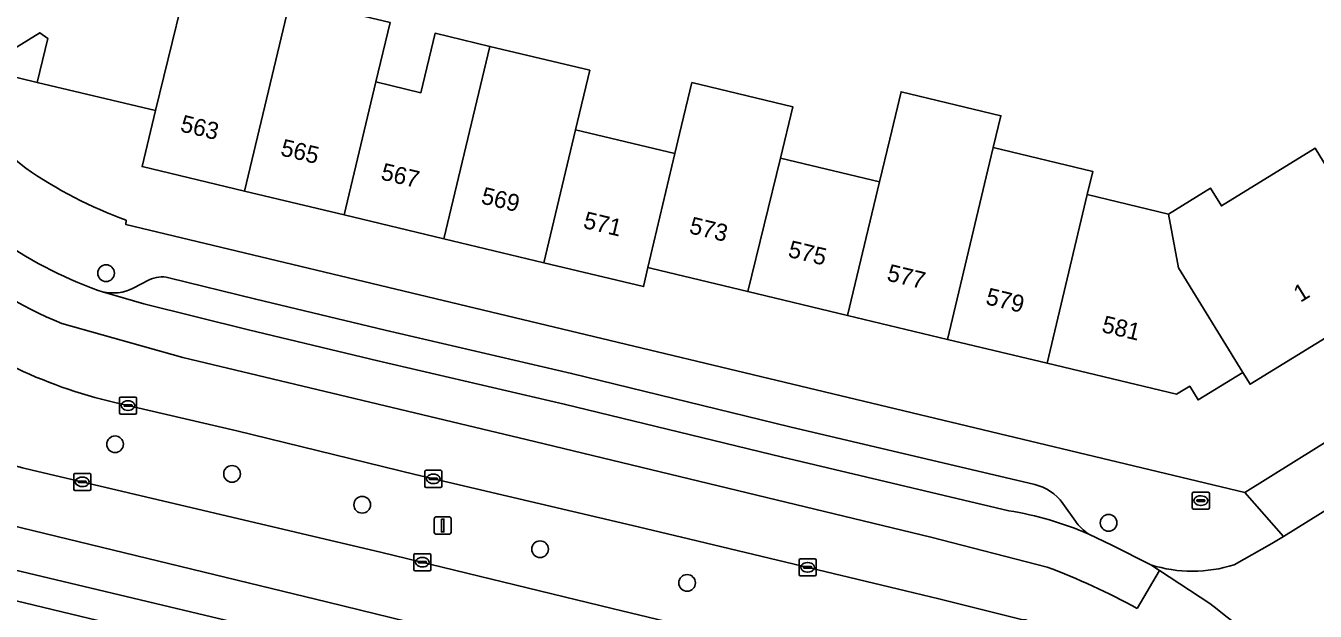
# Model space of a CAD drawing. Extents: x 157767 to 159172, y 387839 to 389425.
# Drawn here: x 158644.5 to 158720.1, y 388142.5 to 388176.8 of the extents above; entities that cross this region are included whole.
import ezdxf

# ---------------------------------------------------------------- set-up
doc = ezdxf.new("R2010")
doc.units = 0
for name, color, linetype in [('IMGEO_Berm_groen', 7, 'Continuous'), ('IMGEO_Boom', 7, 'Continuous'), ('IMGEO_Brandkraan', 7, 'Continuous'), ('IMGEO_Erf', 7, 'Continuous'), ('IMGEO_Kolk', 7, 'Continuous'), ('IMGEO_Lichtmast', 7, 'Continuous'), ('IMGEO_Pand', 7, 'Continuous'), ('IMGEO_Pand_nummerreeks', 7, 'Continuous'), ('IMGEO_Pand_overbouw', 7, 'Continuous'), ('IMGEO_Parkeervlak_open', 7, 'Continuous'), ('IMGEO_Rijbaan_lokaal_gesloten', 7, 'Continuous'), ('IMGEO_Rijbaan_lokaal_open', 7, 'Continuous'), ('IMGEO_Voetpad_open', 7, 'Continuous')]:
    doc.layers.add(name, color=color, linetype=linetype)

msp = doc.modelspace()

# ---------------------------------------------------------------- linework, layer by layer
at = {"layer": 'IMGEO_Berm_groen'}
for points in [[(158667.296, 388150.548), (158656.841, 388153.114), (158649.695, 388154.768)], [(158645.432, 388150.672), (158665.345, 388145.992), (158678.854, 388142.706), (158696.862, 388138.362), (158697.567, 388138.192), (158699.866, 388138.031)], [(158702.855, 388142.067), (158698.004, 388143.26), (158696.05, 388143.74), (158682.917, 388146.888), (158680.041, 388147.562), (158667.296, 388150.548)]]:
    msp.add_lwpolyline(points, dxfattribs=at)
for centre, radius, start, end in [((158656.169, 388182.727), 28.699, 231.06301, 256.96233), ((158651.465, 388178.109), 28.093, 238.29474, 257.59871)]:
    msp.add_arc(centre, radius, start, end, dxfattribs=at)
at = {"layer": 'IMGEO_Boom'}
for centre in [(158649.176, 388162.346), (158649.706, 388152.323), (158656.563, 388150.59), (158664.196, 388148.781), (158707.96, 388147.722), (158674.622, 388146.175), (158683.245, 388144.202)]:
    msp.add_circle(centre, 0.489, dxfattribs=at)
at = {"layer": 'IMGEO_Brandkraan'}
for p, q in [((158712.865, 388148.597), (158712.865, 388149.449)), ((158712.94, 388149.523), (158713.792, 388149.523)), ((158713.353, 388149.303), (158713.378, 388149.303)), ((158713.866, 388149.449), (158713.866, 388148.597)), ((158713.124, 388149.017), (158713.124, 388149.029)), ((158713.562, 388148.98), (158713.164, 388148.98)), ((158713.167, 388149.066), (158713.565, 388149.066)), ((158713.376, 388148.743), (158713.351, 388148.743)), ((158713.608, 388149.029), (158713.608, 388149.017)), ((158713.792, 388148.523), (158712.94, 388148.523))]:
    msp.add_line(p, q, dxfattribs=at)
for points in [[(158712.865, 388148.597), (158712.865, 388149.449)], [(158712.94, 388149.523), (158713.792, 388149.523)], [(158713.866, 388149.449), (158713.866, 388148.597)], [(158713.792, 388148.523), (158712.94, 388148.523)]]:
    msp.add_lwpolyline(points, dxfattribs=at)
for centre, radius, start, end in [((158712.942, 388149.447), 0.0765, 91.55205, 178.44795), ((158712.942, 388149.447), 0.0765, 91.55205, 178.44795), ((158713.79, 388149.447), 0.0765, 1.55205, 88.44795), ((158713.79, 388149.447), 0.0765, 1.55205, 88.44795), ((158712.942, 388148.599), 0.0765, 181.55205, 268.44795), ((158712.942, 388148.599), 0.0765, 181.55205, 268.44795), ((158713.164, 388149.026), 0.0403, 85.87752, 175.75265), ((158713.161, 388149.016), 0.0366, 178.93798, 274.71019), ((158713.565, 388149.023), 0.043, 264.86636, 352.45326), ((158713.569, 388149.028), 0.0386, 1.73085, 96.63898), ((158713.79, 388148.599), 0.0765, 271.55205, 358.44795), ((158713.79, 388148.599), 0.0765, 271.55205, 358.44795)]:
    msp.add_arc(centre, radius, start, end, dxfattribs=at)
for centre, major_axis, ratio, start_param, end_param in [((158713.352, 388149.023), (-0.387, 0.002), 0.722429, 4.712389, 7.853982), ((158713.377, 388149.023), (-0.39, 0.002), 0.717154, 1.570796, 4.712389)]:
    msp.add_ellipse(centre, major_axis=major_axis, ratio=ratio, start_param=start_param, end_param=end_param, dxfattribs=at)
at = {"layer": 'IMGEO_Erf'}
for points in [[(158650.367, 388165.452), (158650.337, 388165.203), (158715.951, 388149.492), (158768.176, 388182.052)], [(158665.837, 388177.027), (158665.004, 388173.549), (158667.637, 388172.919), (158668.469, 388176.398), (158671.687, 388175.628), (158677.536, 388174.228), (158676.704, 388170.749), (158682.532, 388169.354), (158682.806, 388170.501), (158683.525, 388173.507), (158689.436, 388172.093), (158688.717, 388169.087), (158694.528, 388167.696), (158695.127, 388170.2), (158695.79, 388172.971), (158701.64, 388171.572), (158701.192, 388169.7), (158707.027, 388168.305), (158706.703, 388166.947), (158711.467, 388165.807), (158713.927, 388167.33), (158714.573, 388166.287), (158720.07, 388169.662), (158721.758, 388166.913)], [(158725.067, 388161.247), (158716.251, 388155.836), (158715.824, 388156.53), (158713.204, 388154.921), (158712.713, 388155.722), (158711.947, 388155.252), (158704.35, 388157.07), (158698.505, 388158.469), (158692.655, 388159.869), (158686.804, 388161.269), (158681.174, 388162.616), (158680.952, 388162.669), (158680.689, 388161.556), (158674.839, 388162.956), (158668.989, 388164.356), (158663.139, 388165.756), (158657.29, 388167.155), (158651.29, 388168.591), (158652.073, 388171.866), (158645.146, 388173.524), (158645.761, 388176.093), (158645.303, 388176.425), (158643.052, 388175.044)]]:
    msp.add_lwpolyline(points, dxfattribs=at)
for centre, radius, start, end in [((158660.881, 388188.822), 26.124, 210.21415, 231.08824), ((158658.967, 388189.344), 25.393, 235.19125, 250.20316)]:
    msp.add_arc(centre, radius, start, end, dxfattribs=at)
at = {"layer": 'IMGEO_Kolk'}
for p, q in [((158649.966, 388154.165), (158649.966, 388155.017)), ((158650.041, 388155.091), (158650.893, 388155.091)), ((158650.225, 388154.585), (158650.225, 388154.597)), ((158650.268, 388154.634), (158650.666, 388154.634)), ((158650.454, 388154.871), (158650.479, 388154.871)), ((158650.709, 388154.597), (158650.709, 388154.585)), ((158650.967, 388155.017), (158650.967, 388154.165)), ((158650.893, 388154.091), (158650.041, 388154.091)), ((158650.663, 388154.548), (158650.265, 388154.548)), ((158650.477, 388154.311), (158650.452, 388154.311)), ((158647.282, 388149.695), (158647.282, 388150.547)), ((158647.357, 388150.621), (158648.209, 388150.621)), ((158647.541, 388150.115), (158647.541, 388150.127)), ((158647.979, 388150.078), (158647.581, 388150.078)), ((158647.584, 388150.164), (158647.982, 388150.164)), ((158647.77, 388150.401), (158647.795, 388150.401)), ((158648.025, 388150.127), (158648.025, 388150.115)), ((158648.283, 388150.547), (158648.283, 388149.695)), ((158667.864, 388149.871), (158667.864, 388150.723)), ((158667.939, 388150.797), (158668.791, 388150.797)), ((158668.123, 388150.291), (158668.123, 388150.303)), ((158668.561, 388150.254), (158668.163, 388150.254)), ((158668.166, 388150.34), (158668.564, 388150.34)), ((158668.352, 388150.577), (158668.377, 388150.577)), ((158668.607, 388150.303), (158668.607, 388150.291)), ((158668.865, 388150.723), (158668.865, 388149.871)), ((158648.209, 388149.621), (158647.357, 388149.621)), ((158647.793, 388149.841), (158647.768, 388149.841)), ((158668.791, 388149.797), (158667.939, 388149.797)), ((158668.375, 388150.017), (158668.35, 388150.017)), ((158667.222, 388144.989), (158667.222, 388145.841)), ((158667.297, 388145.915), (158668.149, 388145.915)), ((158667.71, 388145.695), (158667.735, 388145.695)), ((158668.223, 388145.841), (158668.223, 388144.989)), ((158689.812, 388144.688), (158689.812, 388145.54)), ((158689.887, 388145.614), (158690.739, 388145.614)), ((158690.813, 388145.54), (158690.813, 388144.688)), ((158668.149, 388144.915), (158667.297, 388144.915)), ((158667.481, 388145.409), (158667.481, 388145.421)), ((158667.919, 388145.372), (158667.521, 388145.372)), ((158667.524, 388145.458), (158667.922, 388145.458)), ((158667.733, 388145.135), (158667.708, 388145.135)), ((158667.965, 388145.421), (158667.965, 388145.409)), ((158690.071, 388145.108), (158690.071, 388145.12)), ((158690.509, 388145.071), (158690.111, 388145.071)), ((158690.114, 388145.157), (158690.512, 388145.157)), ((158690.323, 388144.834), (158690.298, 388144.834)), ((158690.3, 388145.394), (158690.325, 388145.394)), ((158690.555, 388145.12), (158690.555, 388145.108)), ((158690.739, 388144.614), (158689.887, 388144.614))]:
    msp.add_line(p, q, dxfattribs=at)
for points in [[(158649.966, 388154.165), (158649.966, 388155.017)], [(158650.041, 388155.091), (158650.893, 388155.091)], [(158650.967, 388155.017), (158650.967, 388154.165)], [(158650.893, 388154.091), (158650.041, 388154.091)], [(158647.282, 388149.695), (158647.282, 388150.547)], [(158647.357, 388150.621), (158648.209, 388150.621)], [(158648.283, 388150.547), (158648.283, 388149.695)], [(158667.864, 388149.871), (158667.864, 388150.723)], [(158667.939, 388150.797), (158668.791, 388150.797)], [(158668.865, 388150.723), (158668.865, 388149.871)], [(158648.209, 388149.621), (158647.357, 388149.621)], [(158668.791, 388149.797), (158667.939, 388149.797)], [(158667.222, 388144.989), (158667.222, 388145.841)], [(158667.297, 388145.915), (158668.149, 388145.915)], [(158668.223, 388145.841), (158668.223, 388144.989)], [(158689.812, 388144.688), (158689.812, 388145.54)], [(158689.887, 388145.614), (158690.739, 388145.614)], [(158690.813, 388145.54), (158690.813, 388144.688)], [(158668.149, 388144.915), (158667.297, 388144.915)], [(158690.739, 388144.614), (158689.887, 388144.614)]]:
    msp.add_lwpolyline(points, dxfattribs=at)
for centre, radius, start, end in [((158650.043, 388155.015), 0.0765, 91.55205, 178.44795), ((158650.043, 388155.015), 0.0765, 91.55205, 178.44795), ((158650.265, 388154.594), 0.0403, 85.87752, 175.75265), ((158650.67, 388154.596), 0.0386, 1.73085, 96.63898), ((158650.891, 388155.015), 0.0765, 1.55205, 88.44795), ((158650.891, 388155.015), 0.0765, 1.55205, 88.44795), ((158650.043, 388154.167), 0.0765, 181.55205, 268.44795), ((158650.043, 388154.167), 0.0765, 181.55205, 268.44795), ((158650.262, 388154.584), 0.0366, 178.93798, 274.71019), ((158650.666, 388154.591), 0.043, 264.86636, 352.45326), ((158650.891, 388154.167), 0.0765, 271.55205, 358.44795), ((158650.891, 388154.167), 0.0765, 271.55205, 358.44795), ((158647.359, 388150.545), 0.0765, 91.55205, 178.44795), ((158647.359, 388150.545), 0.0765, 91.55205, 178.44795), ((158647.581, 388150.124), 0.0403, 85.87752, 175.75265), ((158647.578, 388150.114), 0.0366, 178.93798, 274.71019), ((158647.982, 388150.121), 0.043, 264.86636, 352.45326), ((158647.986, 388150.126), 0.0386, 1.73085, 96.63898), ((158648.207, 388150.545), 0.0765, 1.55205, 88.44795), ((158648.207, 388150.545), 0.0765, 1.55205, 88.44795), ((158667.941, 388150.721), 0.0765, 91.55205, 178.44795), ((158667.941, 388150.721), 0.0765, 91.55205, 178.44795), ((158668.163, 388150.3), 0.0403, 85.87752, 175.75265), ((158668.16, 388150.29), 0.0366, 178.93798, 274.71019), ((158668.564, 388150.297), 0.043, 264.86636, 352.45326), ((158668.568, 388150.302), 0.0386, 1.73085, 96.63898), ((158668.789, 388150.721), 0.0765, 1.55205, 88.44795), ((158668.789, 388150.721), 0.0765, 1.55205, 88.44795), ((158647.359, 388149.697), 0.0765, 181.55205, 268.44795), ((158647.359, 388149.697), 0.0765, 181.55205, 268.44795), ((158648.207, 388149.697), 0.0765, 271.55205, 358.44795), ((158648.207, 388149.697), 0.0765, 271.55205, 358.44795), ((158667.941, 388149.873), 0.0765, 181.55205, 268.44795), ((158667.941, 388149.873), 0.0765, 181.55205, 268.44795), ((158668.789, 388149.873), 0.0765, 271.55205, 358.44795), ((158668.789, 388149.873), 0.0765, 271.55205, 358.44795), ((158667.299, 388145.839), 0.0765, 91.55205, 178.44795), ((158667.299, 388145.839), 0.0765, 91.55205, 178.44795), ((158668.147, 388145.839), 0.0765, 1.55205, 88.44795), ((158668.147, 388145.839), 0.0765, 1.55205, 88.44795), ((158689.889, 388145.538), 0.0765, 91.55205, 178.44795), ((158689.889, 388145.538), 0.0765, 91.55205, 178.44795), ((158690.737, 388145.538), 0.0765, 1.55205, 88.44795), ((158690.737, 388145.538), 0.0765, 1.55205, 88.44795), ((158667.299, 388144.991), 0.0765, 181.55205, 268.44795), ((158667.299, 388144.991), 0.0765, 181.55205, 268.44795), ((158667.521, 388145.418), 0.0403, 85.87752, 175.75265), ((158667.518, 388145.408), 0.0366, 178.93798, 274.71019), ((158667.922, 388145.415), 0.043, 264.86636, 352.45326), ((158667.926, 388145.42), 0.0386, 1.73085, 96.63898), ((158668.147, 388144.991), 0.0765, 271.55205, 358.44795), ((158668.147, 388144.991), 0.0765, 271.55205, 358.44795), ((158690.111, 388145.117), 0.0403, 85.87752, 175.75265), ((158690.108, 388145.107), 0.0366, 178.93798, 274.71019), ((158690.512, 388145.114), 0.043, 264.86636, 352.45326), ((158690.516, 388145.119), 0.0386, 1.73085, 96.63898), ((158689.889, 388144.69), 0.0765, 181.55205, 268.44795), ((158689.889, 388144.69), 0.0765, 181.55205, 268.44795), ((158690.737, 388144.69), 0.0765, 271.55205, 358.44795), ((158690.737, 388144.69), 0.0765, 271.55205, 358.44795)]:
    msp.add_arc(centre, radius, start, end, dxfattribs=at)
for centre, major_axis, ratio, start_param, end_param in [((158650.453, 388154.591), (-0.387, 0.002), 0.722429, 4.712389, 7.853982), ((158650.478, 388154.591), (-0.39, 0.002), 0.717154, 1.570796, 4.712389), ((158647.769, 388150.121), (-0.387, 0.002), 0.722429, 4.712389, 7.853982), ((158647.794, 388150.121), (-0.39, 0.002), 0.717154, 1.570796, 4.712389), ((158668.351, 388150.297), (-0.387, 0.002), 0.722429, 4.712389, 7.853982), ((158668.376, 388150.297), (-0.39, 0.002), 0.717154, 1.570796, 4.712389), ((158667.709, 388145.415), (-0.387, 0.002), 0.722429, 4.712389, 7.853982), ((158667.734, 388145.415), (-0.39, 0.002), 0.717154, 1.570796, 4.712389), ((158690.299, 388145.114), (-0.387, 0.002), 0.722429, 4.712389, 7.853982), ((158690.324, 388145.114), (-0.39, 0.002), 0.717154, 1.570796, 4.712389)]:
    msp.add_ellipse(centre, major_axis=major_axis, ratio=ratio, start_param=start_param, end_param=end_param, dxfattribs=at)
at = {"layer": 'IMGEO_Lichtmast'}
for p, q in [((158668.421, 388147.165), (158668.421, 388147.965)), ((158668.421, 388147.965), (158668.421, 388147.165)), ((158668.521, 388148.065), (158669.311, 388148.065)), ((158669.311, 388148.065), (158668.521, 388148.065)), ((158669.411, 388147.965), (158669.411, 388147.165)), ((158669.411, 388147.165), (158669.411, 388147.965)), ((158669.311, 388147.065), (158668.521, 388147.065)), ((158668.521, 388147.065), (158669.311, 388147.065))]:
    msp.add_line(p, q, dxfattribs=at)
msp.add_lwpolyline([(158668.841, 388147.94), (158668.991, 388147.94), (158668.991, 388147.19), (158668.841, 388147.19), (158668.841, 388147.94)], dxfattribs=at)
for centre, start, end in [((158668.521, 388147.965), 90, 180), ((158668.521, 388147.965), 90, 180), ((158669.311, 388147.965), 0, 90), ((158669.311, 388147.965), 360, 90), ((158668.521, 388147.165), 180, 270), ((158668.521, 388147.165), 180, 270), ((158669.311, 388147.165), 270, 0), ((158669.311, 388147.165), 270, 0)]:
    msp.add_arc(centre, 0.1, start, end, dxfattribs=at)
at = {"layer": 'IMGEO_Pand'}
for points in [[(158654.026, 388179.853), (158653.869, 388179.891), (158654.069, 388180.729), (158649.399, 388181.847), (158647.073, 388185.635), (158639.217, 388180.813), (158639.28, 388180.711), (158639.493, 388180.842), (158643.052, 388175.044), (158645.303, 388176.425), (158645.761, 388176.093), (158645.146, 388173.524), (158652.073, 388171.866)], [(158657.29, 388167.155), (158659.988, 388178.427), (158654.026, 388179.853), (158652.073, 388171.866), (158651.29, 388168.591)], [(158665.004, 388173.549), (158665.837, 388177.027), (158659.988, 388178.427), (158657.29, 388167.155), (158663.139, 388165.756)], [(158671.687, 388175.628), (158668.469, 388176.398), (158667.637, 388172.919), (158665.004, 388173.549), (158663.139, 388165.756), (158668.989, 388164.356)], [(158676.704, 388170.749), (158677.536, 388174.228), (158671.687, 388175.628), (158668.989, 388164.356), (158674.839, 388162.956)], [(158688.717, 388169.087), (158689.436, 388172.093), (158683.525, 388173.507), (158682.806, 388170.501), (158682.532, 388169.354), (158680.952, 388162.669), (158681.174, 388162.616), (158686.804, 388161.269)], [(158700.977, 388168.801), (158701.192, 388169.7), (158701.64, 388171.572), (158695.79, 388172.971), (158695.127, 388170.2), (158694.528, 388167.696), (158692.655, 388159.869), (158698.505, 388158.469)], [(158682.532, 388169.354), (158676.704, 388170.749), (158674.839, 388162.956), (158680.689, 388161.556), (158680.952, 388162.669)], [(158686.804, 388161.269), (158692.655, 388159.869), (158694.528, 388167.696), (158688.717, 388169.087)], [(158700.977, 388168.801), (158698.505, 388158.469), (158704.35, 388157.07), (158706.703, 388166.947), (158707.027, 388168.305), (158701.192, 388169.7)], [(158721.758, 388166.913), (158720.07, 388169.662), (158714.573, 388166.287), (158713.927, 388167.33), (158711.467, 388165.807), (158712.066, 388162.649), (158715.824, 388156.53), (158716.251, 388155.836), (158725.067, 388161.247), (158725.19, 388161.323)], [(158706.703, 388166.947), (158704.35, 388157.07), (158711.947, 388155.252), (158712.713, 388155.722), (158713.204, 388154.921), (158715.824, 388156.53), (158712.066, 388162.649), (158711.467, 388165.807)]]:
    msp.add_lwpolyline(points, close=True, dxfattribs=at)
at = {"layer": 'IMGEO_Pand_overbouw'}
msp.add_lwpolyline([(158643.052, 388175.044), (158643.617, 388174.123), (158643.784, 388173.85), (158644.096, 388173.775), (158645.146, 388173.524), (158645.761, 388176.093), (158645.303, 388176.425)], close=True, dxfattribs=at)
at = {"layer": 'IMGEO_Parkeervlak_open'}
for points in [[(158651.712, 388161.947), (158650.769, 388161.468)], [(158703.629, 388149.966), (158689.265, 388153.351), (158676.469, 388156.47), (158665.541, 388159.008), (158657.957, 388160.819), (158652.855, 388162.078)], [(158648.979, 388161.259), (158651.386, 388160.545), (158657.523, 388159.03), (158665.119, 388157.216), (158676.043, 388154.679), (158688.836, 388151.561), (158702.108, 388148.433)], [(158706.009, 388147.818), (158705.271, 388148.859)], [(158696.145, 388132.346), (158694.421, 388132.848), (158672.619, 388138.031), (158660.276, 388141.048), (158643.375, 388145.058)], [(158642.265, 388143.54), (158693.074, 388131.323)]]:
    msp.add_lwpolyline(points, dxfattribs=at)
for centre, radius, start, end in [((158649.59, 388163.794), 2.608, 256.44484, 296.87454), ((158652.458, 388160.486), 1.641, 76.01585, 117.06051), ((158702.989, 388147.245), 2.795, 35.26659, 76.75946), ((158698.835, 388128.45), 20.249, 66.81571, 80.69853), ((158708.288, 388149.431), 2.792, 215.28708, 237.96078)]:
    msp.add_arc(centre, radius, start, end, dxfattribs=at)
at = {"layer": 'IMGEO_Rijbaan_lokaal_gesloten'}
for points in [[(158702.108, 388148.433), (158688.836, 388151.561), (158676.043, 388154.679), (158665.119, 388157.216), (158657.523, 388159.03), (158651.386, 388160.545), (158648.979, 388161.259), (158648.712, 388161.339)], [(158646.582, 388159.393), (158653.673, 388157.402), (158674.306, 388152.48), (158697.539, 388146.885), (158704.354, 388145.125)], [(158704.354, 388145.125), (158697.539, 388146.885), (158674.306, 388152.48), (158653.673, 388157.402), (158646.582, 388159.393)], [(158649.695, 388154.768), (158656.841, 388153.114), (158667.296, 388150.548), (158680.041, 388147.562), (158682.917, 388146.888), (158696.05, 388143.74), (158698.004, 388143.26), (158702.855, 388142.067), (158703.085, 388142.047), (158704.28, 388141.566), (158705.476, 388140.952), (158708.524, 388139.165), (158710.054, 388138.14), (158711.592, 388136.986), (158713.157, 388135.67), (158714.642, 388134.252), (158714.968, 388133.743), (158716.186, 388131.703), (158716.731, 388130.827), (158717.852, 388129.025), (158725.178, 388117.248)], [(158726.373, 388106.161), (158721.077, 388114.643), (158715.254, 388123.838), (158713.652, 388126.449), (158713.046, 388127.438), (158712.568, 388128.281), (158711.679, 388129.084), (158710.125, 388130.777), (158708.377, 388132.377), (158706.878, 388133.633), (158705.213, 388134.72), (158703.592, 388135.668), (158701.693, 388136.525), (158699.357, 388137.377), (158697.567, 388138.192), (158696.862, 388138.362), (158678.854, 388142.706), (158665.345, 388145.992), (158645.432, 388150.672)], [(158696.239, 388134.766), (158682.624, 388138.085), (158662.189, 388143.066), (158642.92, 388147.742)], [(158642.92, 388147.742), (158662.189, 388143.066), (158682.624, 388138.085), (158696.239, 388134.766)], [(158709.631, 388142.704), (158710.946, 388144.924), (158710.433, 388145.261), (158708.145, 388146.419), (158706.807, 388147.064)], [(158643.375, 388145.058), (158660.276, 388141.048), (158672.619, 388138.031), (158694.421, 388132.848), (158696.145, 388132.346), (158696.262, 388132.312)], [(158713.89, 388142.988), (158710.946, 388144.924), (158709.631, 388142.704)]]:
    msp.add_lwpolyline(points, dxfattribs=at)
for centre, radius, start, end in [((158657.821, 388186.041), 28.921, 215.82071, 247.13254), ((158657.821, 388186.041), 28.921, 215.82071, 247.13254), ((158657.039, 388184.543), 24.653, 234.35583, 250.2601), ((158656.169, 388182.727), 28.699, 231.06301, 256.96233), ((158651.465, 388178.109), 28.093, 238.29474, 257.59871), ((158698.835, 388128.45), 20.249, 66.81571, 80.69853), ((158691.294, 388109.697), 37.759, 60.94581, 69.76445), ((158691.294, 388109.697), 37.759, 60.94581, 69.76445), ((158697.094, 388120.135), 28.361, 36.35205, 53.68587)]:
    msp.add_arc(centre, radius, start, end, dxfattribs=at)
at = {"layer": 'IMGEO_Rijbaan_lokaal_open'}
for points in [[(158776.519, 388171.716), (158771.15, 388179.789), (158770.871, 388179.63), (158761.897, 388173.962), (158752.849, 388168.293), (158741.723, 388161.435), (158731.615, 388155.157), (158730.286, 388154.349), (158724.598, 388150.885), (158723.834, 388150.412), (158718.207, 388146.927), (158717.535, 388146.511), (158715.318, 388145.265)], [(158710.433, 388145.261), (158710.946, 388144.924), (158713.89, 388142.988)]]:
    msp.add_lwpolyline(points, dxfattribs=at)
for centre, radius, start, end in [((158712.869, 388153.008), 8.121, 252.54401, 287.54982), ((158697.094, 388120.135), 28.361, 36.35205, 53.68587)]:
    msp.add_arc(centre, radius, start, end, dxfattribs=at)
at = {"layer": 'IMGEO_Voetpad_open'}
for points in [[(158589.589, 388205.583), (158591.997, 388201.731), (158596.931, 388193.835), (158605.271, 388180.491), (158606.085, 388179.189), (158628.661, 388143.066), (158640.111, 388140.318), (158641.347, 388140.021), (158691.944, 388127.877), (158693.074, 388131.323), (158642.265, 388143.54)], [(158768.176, 388182.052), (158715.951, 388149.492), (158718.207, 388146.927), (158723.834, 388150.412)], [(158715.318, 388145.265), (158717.535, 388146.511), (158718.207, 388146.927), (158715.951, 388149.492), (158650.337, 388165.203), (158650.367, 388165.452)], [(158650.769, 388161.468), (158651.712, 388161.947)], [(158652.855, 388162.078), (158657.957, 388160.819), (158665.541, 388159.008), (158676.469, 388156.47), (158689.265, 388153.351), (158703.629, 388149.966)], [(158648.712, 388161.339), (158648.979, 388161.259)], [(158705.271, 388148.859), (158706.009, 388147.818)], [(158706.807, 388147.064), (158708.145, 388146.419), (158710.433, 388145.261)]]:
    msp.add_lwpolyline(points, dxfattribs=at)
for centre, radius, start, end in [((158660.881, 388188.822), 26.124, 210.21415, 231.08824), ((158658.967, 388189.344), 25.393, 235.19125, 250.20316), ((158657.039, 388184.543), 24.653, 234.35583, 250.2601), ((158649.59, 388163.794), 2.608, 256.44484, 296.87454), ((158652.458, 388160.486), 1.641, 76.01585, 117.06051), ((158702.989, 388147.245), 2.795, 35.26659, 76.75946), ((158708.288, 388149.431), 2.792, 215.28708, 237.96078), ((158712.869, 388153.008), 8.121, 252.54401, 287.54982)]:
    msp.add_arc(centre, radius, start, end, dxfattribs=at)

# ---------------------------------------------------------------- texts
at = {"layer": 'IMGEO_Pand_nummerreeks'}
for s, rotation, p in [('563', 346.54253, (158653.477, 388170.659)), ('565', 346.54122, (158659.357, 388169.252)), ('567', 346.54122, (158665.236, 388167.845)), ('569', 346.54253, (158671.116, 388166.438)), ('571', 346.54122, (158677.105, 388165.005)), ('573', 346.54122, (158683.318, 388164.694)), ('575', 346.54223, (158689.112, 388163.308)), ('577', 346.54122, (158694.906, 388161.921)), ('579', 346.54223, (158700.7, 388160.535)), ('1', 31.54133, (158719.203, 388160.604)), ('581', 346.54192, (158707.504, 388158.906))]:
    msp.add_text(s, height=1, rotation=rotation, dxfattribs=at).set_placement(p)

doc.saveas('drawing.dxf')
